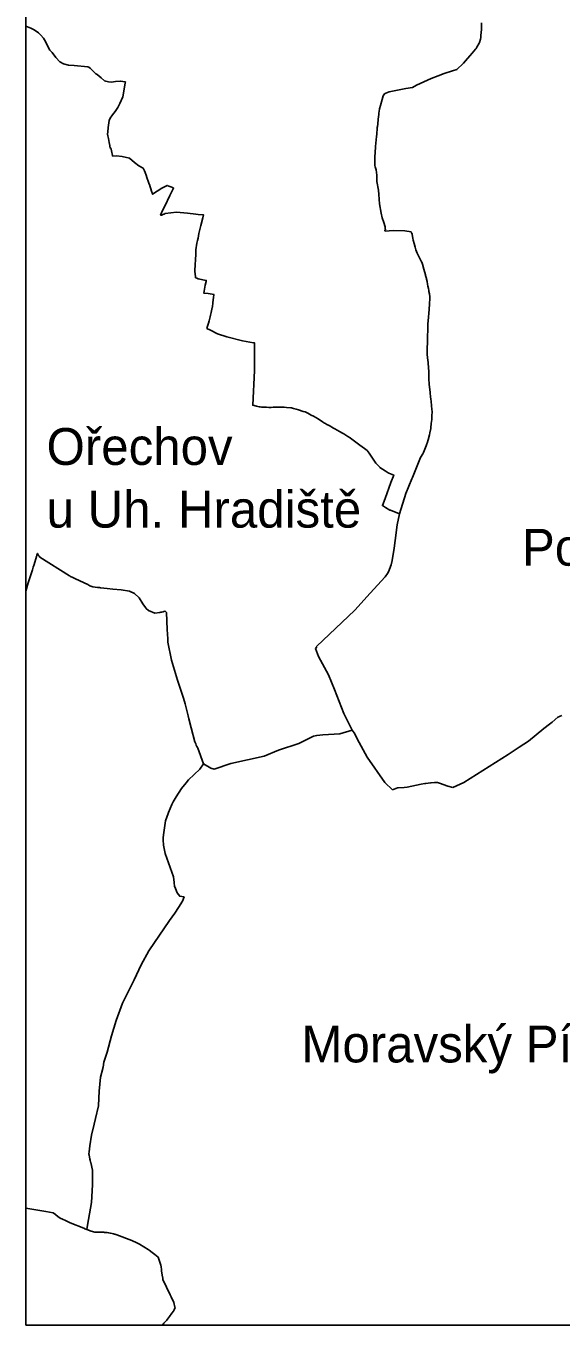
# Model space of a CAD drawing. Extents: x -552716 to -540720, y -1192685 to -1177912.
# Drawn here: x -549696 to -547709, y -1188366 to -1183546 of the extents above; entities that cross this region are included whole.
import ezdxf

# ---------------------------------------------------------------- set-up
doc = ezdxf.new("R2010")
doc.units = 0
doc.layers.add('Vrstva 1', color=7, linetype='Continuous')
doc.layers.add('Vrstva 60', color=7, linetype='Continuous')

msp = doc.modelspace()

# ---------------------------------------------------------------- linework, layer by layer
at = {"layer": 'Vrstva 1'}
for p, q in [((-548006.7, -1183581.2), (-548004.7, -1183558.7)), ((-548004.4, -1183547), (-548004.7, -1183533.8)), ((-548004.7, -1183558.7), (-548004.2, -1183553.8)), ((-548004.3, -1183552), (-548004.4, -1183547)), ((-548004.2, -1183553.8), (-548004.3, -1183552)), ((-548022.2, -1183624.6), (-548013.1, -1183609.1)), ((-548013.1, -1183609.1), (-548012.1, -1183607.4)), ((-548012.1, -1183607.4), (-548008.8, -1183594.9)), ((-548008.8, -1183594.9), (-548008.7, -1183594.2)), ((-548008.7, -1183594.2), (-548007.7, -1183588.1)), ((-548007.7, -1183588.1), (-548006.8, -1183582.7)), ((-548006.8, -1183582.7), (-548006.7, -1183581.2)), ((-548064, -1183675.4), (-548047.7, -1183656.8)), ((-548047.7, -1183656.8), (-548039.1, -1183646.4)), ((-548039.1, -1183646.4), (-548027, -1183631.6)), ((-548027, -1183631.6), (-548024.8, -1183628.9)), ((-548024.8, -1183628.9), (-548022.2, -1183624.6)), ((-548143.3, -1183722.5), (-548112.7, -1183712.6)), ((-548112.7, -1183712.6), (-548096.6, -1183707.4)), ((-548096.6, -1183707.4), (-548089.5, -1183700.7)), ((-548089.5, -1183700.7), (-548079.4, -1183691.2)), ((-548079.4, -1183691.2), (-548071.6, -1183684)), ((-548071.6, -1183684), (-548071.3, -1183683.6)), ((-548071.3, -1183683.6), (-548064, -1183675.4)), ((-548260.9, -1183773.8), (-548245.8, -1183765.2)), ((-548245.8, -1183765.2), (-548219, -1183753.4)), ((-548219, -1183753.4), (-548191.5, -1183741.2)), ((-548191.5, -1183741.2), (-548165.2, -1183730.9)), ((-548165.2, -1183730.9), (-548143.3, -1183722.5)), ((-548374, -1183818.8), (-548370.3, -1183805.3)), ((-548370.3, -1183805.3), (-548364.5, -1183797.2)), ((-548364.5, -1183797.2), (-548359.5, -1183795)), ((-548359.5, -1183795), (-548347.3, -1183789.6)), ((-548347.3, -1183789.6), (-548285.2, -1183778.3)), ((-548285.2, -1183778.3), (-548260.9, -1183773.8)), ((-548385.5, -1183868.9), (-548383.8, -1183854.5)), ((-548383.8, -1183854.5), (-548383.3, -1183852.7)), ((-548383.3, -1183852.7), (-548380.1, -1183840.7)), ((-548380.1, -1183840.7), (-548374, -1183818.8)), ((-548391.1, -1183918.4), (-548390.1, -1183909.8)), ((-548390.1, -1183909.8), (-548389.4, -1183904.1)), ((-548389.4, -1183904.1), (-548388.7, -1183897.4)), ((-548388.7, -1183897.4), (-548388, -1183891.4)), ((-548388, -1183891.4), (-548386.1, -1183874.7)), ((-548386.1, -1183874.7), (-548385.5, -1183868.9)), ((-548397.8, -1183993.5), (-548394.5, -1183955.3)), ((-548394.5, -1183955.3), (-548393.8, -1183947.2)), ((-548393.8, -1183947.2), (-548391.8, -1183924.9)), ((-548391.8, -1183924.9), (-548391.6, -1183923)), ((-548391.6, -1183923), (-548391.1, -1183918.4)), ((-548399.8, -1184016.1), (-548397.8, -1183993.5)), ((-548401, -1184061.4), (-548400.6, -1184046.8)), ((-548400.6, -1184046.8), (-548400.2, -1184030.6)), ((-548400.2, -1184030.6), (-548399.9, -1184016.3)), ((-548399.9, -1184016.3), (-548399.8, -1184016.1)), ((-548400.6, -1184062.9), (-548401, -1184061.4)), ((-548398.9, -1184068.6), (-548400.6, -1184062.9)), ((-548395.9, -1184079), (-548398.9, -1184068.6)), ((-548393.4, -1184099.7), (-548395.9, -1184079)), ((-548393.2, -1184123.4), (-548393.4, -1184099.7)), ((-548387.7, -1184155.4), (-548393.2, -1184123.4)), ((-548385.8, -1184171), (-548387.7, -1184155.4)), ((-548385.2, -1184188.9), (-548385.8, -1184171)), ((-548382.9, -1184206.2), (-548385.2, -1184188.9)), ((-548377.2, -1184240.8), (-548382.9, -1184206.2)), ((-548373.8, -1184257.4), (-548377.2, -1184240.8)), ((-548367.4, -1184274.9), (-548373.8, -1184257.4)), ((-548362, -1184291.2), (-548367.4, -1184274.9)), ((-548361.9, -1184294.6), (-548362, -1184291.2)), ((-548361.8, -1184297.2), (-548361.9, -1184294.6)), ((-548363.2, -1184302.9), (-548361.6, -1184302.8)), ((-548363.1, -1184304.2), (-548363.2, -1184302.9)), ((-548362.8, -1184307), (-548363.1, -1184304.2)), ((-548333.1, -1184304.8), (-548362.8, -1184307)), ((-548361.8, -1184298.9), (-548361.8, -1184297.2)), ((-548361.7, -1184300.9), (-548361.8, -1184298.9)), ((-548361.6, -1184301.8), (-548361.7, -1184300.9)), ((-548361.6, -1184302.8), (-548361.6, -1184301.8)), ((-548288.8, -1184306.2), (-548333.1, -1184304.8)), ((-548265.2, -1184310.1), (-548288.8, -1184306.2)), ((-548264.6, -1184314.4), (-548265.2, -1184310.1)), ((-548264.5, -1184314.7), (-548264.6, -1184314.4)), ((-548263, -1184314.7), (-548264.5, -1184314.7)), ((-548262.7, -1184318.2), (-548263, -1184314.7)), ((-548260.9, -1184327.4), (-548262.7, -1184318.2)), ((-548259.7, -1184333.5), (-548260.9, -1184327.4)), ((-548258.3, -1184340.5), (-548259.7, -1184333.5)), ((-548254.7, -1184353.3), (-548258.3, -1184340.5)), ((-548251, -1184366), (-548254.7, -1184353.3)), ((-548248.1, -1184376.4), (-548251, -1184366)), ((-548243.4, -1184388.5), (-548248.1, -1184376.4)), ((-548241.6, -1184393.3), (-548243.4, -1184388.5)), ((-548227.1, -1184421), (-548241.6, -1184393.3)), ((-548226.5, -1184422.1), (-548227.1, -1184421)), ((-548224.2, -1184429.8), (-548226.5, -1184422.1)), ((-548218.9, -1184447.9), (-548224.2, -1184429.8)), ((-548212.6, -1184469.4), (-548218.9, -1184447.9)), ((-548212.1, -1184471.5), (-548212.6, -1184469.4)), ((-548209.2, -1184483), (-548212.1, -1184471.5)), ((-548208.8, -1184484.7), (-548209.2, -1184483)), ((-548206.9, -1184494), (-548208.8, -1184484.7)), ((-548205, -1184503.2), (-548206.9, -1184494)), ((-548203.3, -1184511.3), (-548205, -1184503.2)), ((-548201.7, -1184519.5), (-548203.3, -1184511.3)), ((-548200.2, -1184527.7), (-548201.7, -1184519.5)), ((-548199.7, -1184530.7), (-548200.2, -1184527.7)), ((-548198.3, -1184540.2), (-548199.7, -1184530.7)), ((-548198.6, -1184591.1), (-548198.2, -1184582.5)), ((-548196.7, -1184550.6), (-548198.3, -1184540.2)), ((-548198.2, -1184582.5), (-548196.7, -1184550.6)), ((-548202.8, -1184639.3), (-548199.2, -1184598)), ((-548199.2, -1184598), (-548198.6, -1184591.1)), ((-548205.2, -1184701.7), (-548204.4, -1184669.7)), ((-548204.4, -1184669.7), (-548203.9, -1184653.7)), ((-548203.9, -1184650.9), (-548202.8, -1184639.3)), ((-548203.9, -1184653.7), (-548203.9, -1184650.9)), ((-548206.4, -1184745.6), (-548205.6, -1184716.2)), ((-548205.6, -1184716.2), (-548205.2, -1184701.7)), ((-548206.8, -1184762), (-548206.4, -1184745.6)), ((-548204.6, -1184778.7), (-548206.8, -1184762)), ((-548203.8, -1184785.1), (-548204.6, -1184778.7)), ((-548203, -1184796), (-548203.8, -1184785.1)), ((-548201.7, -1184813.7), (-548203, -1184796)), ((-548200.6, -1184828.4), (-548201.7, -1184813.7)), ((-548200.5, -1184830.3), (-548200.6, -1184828.4)), ((-548199.6, -1184857.9), (-548200.5, -1184830.3)), ((-548199, -1184872.6), (-548199.6, -1184857.9)), ((-548198.9, -1184875.3), (-548199, -1184872.6)), ((-548197.7, -1184886.6), (-548198.9, -1184875.3)), ((-548195.5, -1184905.2), (-548197.7, -1184886.6)), ((-548195.2, -1184908.1), (-548195.5, -1184905.2)), ((-548193.7, -1184920.7), (-548195.2, -1184908.1)), ((-548192.4, -1184932.4), (-548193.7, -1184920.7)), ((-548192, -1184936.7), (-548192.4, -1184932.4)), ((-548191.5, -1184941.7), (-548192, -1184936.7)), ((-548190.5, -1184951.3), (-548191.5, -1184941.7)), ((-548190, -1184956.1), (-548190.5, -1184951.3)), ((-548189.3, -1184966.2), (-548190, -1184956.1)), ((-548188.4, -1184979), (-548189.3, -1184966.2)), ((-548191.3, -1185022.6), (-548190.2, -1185012.7)), ((-548190.2, -1185012.7), (-548189.5, -1185007)), ((-548189.5, -1185007), (-548189.3, -1185001.8)), ((-548189.3, -1185001.8), (-548188.9, -1184991.1)), ((-548188.9, -1184991.1), (-548188.4, -1184979)), ((-548203.2, -1185081.1), (-548198.2, -1185062.8)), ((-548198.2, -1185062.8), (-548196.6, -1185055.1)), ((-548196.6, -1185055.1), (-548193.3, -1185039)), ((-548193.3, -1185039), (-548192.9, -1185036.1)), ((-548192.9, -1185036.1), (-548191.3, -1185022.6)), ((-548215, -1185115.8), (-548210.4, -1185103.9)), ((-548210.4, -1185103.9), (-548207.5, -1185096.4)), ((-548207.5, -1185096.4), (-548206.8, -1185094.1)), ((-548206.8, -1185094.1), (-548203.2, -1185081.1)), ((-548256.1, -1185209.4), (-548231.2, -1185147.6)), ((-548231.2, -1185147.6), (-548222, -1185134)), ((-548222, -1185134), (-548219.8, -1185128.2)), ((-548219.8, -1185128.2), (-548215, -1185115.8)), ((-548261.1, -1185221.7), (-548256.1, -1185209.4)), ((-548285, -1185280.5), (-548262.8, -1185225.8)), ((-548262.8, -1185225.8), (-548261.1, -1185221.7)), ((-548309, -1185355.8), (-548285, -1185280.5)), ((-548317.9, -1185397.5), (-548309, -1185355.8)), ((-548325.6, -1185454.8), (-548317.9, -1185397.5)), ((-548335.9, -1185528.9), (-548328.3, -1185483.6)), ((-548328.3, -1185483.6), (-548325.6, -1185454.8)), ((-548350.1, -1185570.8), (-548339.8, -1185544.8)), ((-548339.8, -1185544.8), (-548335.9, -1185528.9)), ((-548418.4, -1185650.6), (-548362.5, -1185589.4)), ((-548362.5, -1185589.4), (-548353.5, -1185578)), ((-548353.5, -1185578), (-548350.1, -1185570.8)), ((-548475, -1185713.1), (-548418.4, -1185650.6)), ((-548617.1, -1185848), (-548475, -1185713.1)), ((-548621.6, -1185855.7), (-548616.4, -1185850.1)), ((-548610.1, -1185885.7), (-548621.6, -1185855.7)), ((-548616.4, -1185850.1), (-548617.1, -1185848)), ((-548573.1, -1185953.8), (-548610.1, -1185885.7)), ((-548551, -1186008.4), (-548573.1, -1185953.8)), ((-548516.1, -1186097.6), (-548551, -1186008.4)), ((-548486.2, -1186156.6), (-548516.1, -1186097.6)), ((-547721.2, -1186110.7), (-547742.6, -1186128.8)), ((-547714.5, -1186108), (-547721.2, -1186110.7)), ((-547712.1, -1186107.1), (-547714.5, -1186108)), ((-547706.2, -1186104.7), (-547712.1, -1186107.1)), ((-548484.8, -1186159.4), (-548486.2, -1186156.6)), ((-548478, -1186168.9), (-548484.8, -1186159.4)), ((-548458.7, -1186204.9), (-548478, -1186168.9)), ((-547772.7, -1186153.1), (-547829.7, -1186199.2)), ((-547751.6, -1186136.1), (-547772.7, -1186153.1)), ((-547742.6, -1186128.8), (-547751.6, -1186136.1)), ((-548429.7, -1186259.2), (-548458.7, -1186204.9)), ((-547865.4, -1186221.9), (-547905.9, -1186248.9)), ((-547829.7, -1186199.2), (-547865.4, -1186221.9)), ((-548363.5, -1186352.8), (-548429.7, -1186259.2)), ((-547905.9, -1186248.9), (-548070.5, -1186352.8)), ((-548335.6, -1186380.3), (-548363.5, -1186352.8)), ((-548229, -1186359.6), (-548281.2, -1186370.3)), ((-548215.1, -1186357.4), (-548229, -1186359.6)), ((-548211.9, -1186356.8), (-548215.1, -1186357.4)), ((-548194.5, -1186354), (-548211.9, -1186356.8)), ((-548191.4, -1186353.9), (-548194.5, -1186354)), ((-548179.1, -1186353.5), (-548191.4, -1186353.9)), ((-548174.4, -1186353.3), (-548179.1, -1186353.5)), ((-548168.5, -1186353.1), (-548174.4, -1186353.3)), ((-548160.9, -1186355.8), (-548168.5, -1186353.1)), ((-548129.4, -1186367.3), (-548160.9, -1186355.8)), ((-548111.4, -1186372.1), (-548129.4, -1186367.3)), ((-548070.5, -1186352.8), (-548111.4, -1186372.1)), ((-548323, -1186375.8), (-548335.6, -1186380.3)), ((-548316.1, -1186373.3), (-548323, -1186375.8)), ((-548313.9, -1186372.5), (-548316.1, -1186373.3)), ((-548292.2, -1186371.1), (-548313.9, -1186372.5)), ((-548281.2, -1186370.3), (-548292.2, -1186371.1))]:
    msp.add_line(p, q, dxfattribs=at)
for points in [[(-549150.3, -1184145.8), (-549154.5, -1184143.8), (-549165.7, -1184139.6), (-549171.8, -1184137.4), (-549191.3, -1184147.2), (-549225.9, -1184170), (-549226.4, -1184168.6), (-549229.6, -1184158.8), (-549232.3, -1184150.6), (-549235.1, -1184142.2), (-549237.8, -1184133.7), (-549238.2, -1184132.5), (-549240.8, -1184125.3), (-549247, -1184107.9), (-549249.9, -1184099.7), (-549250.2, -1184099.1), (-549253.6, -1184089.1), (-549255.7, -1184083.2), (-549261.1, -1184072.9), (-549277.4, -1184064.2), (-549293.5, -1184051.9), (-549311.8, -1184036.1), (-549339.2, -1184030), (-549360.1, -1184028.1), (-549374.3, -1184028.7), (-549374.8, -1184026.8), (-549378.9, -1184008.9), (-549380.2, -1184003.3), (-549381.4, -1183998.2), (-549383.8, -1183998.1), (-549384.5, -1183993.2), (-549384.8, -1183989.8), (-549386.6, -1183977.8), (-549389.6, -1183963.7), (-549391.8, -1183953.1), (-549393.1, -1183947.6), (-549392.3, -1183939.1), (-549390.7, -1183922.9), (-549388.1, -1183904.9), (-549386.8, -1183896), (-549382.9, -1183888), (-549374.9, -1183875.3), (-549364.7, -1183863.2), (-549354.5, -1183848), (-549347.8, -1183833.7), (-549336.1, -1183808.3), (-549327.4, -1183758.3), (-549326.6, -1183753.5), (-549346.2, -1183750.2), (-549363.5, -1183752.3), (-549371, -1183753.1), (-549378.4, -1183754), (-549389.2, -1183753.3), (-549399.8, -1183750.8), (-549404.3, -1183748.8), (-549416.7, -1183737.7), (-549432.2, -1183726.3), (-549436.8, -1183722.9), (-549440.5, -1183719.5), (-549447.3, -1183712.2), (-549458, -1183702), (-549462, -1183698.2), (-549465.8, -1183697.8), (-549517.3, -1183692.5), (-549537.9, -1183690.9), (-549557, -1183685.9), (-549569.7, -1183678.4), (-549584.7, -1183662.8), (-549598.7, -1183644), (-549607.9, -1183635.3), (-549617.7, -1183616.7), (-549624.1, -1183603.6), (-549630.7, -1183591.5), (-549640.6, -1183580.4), (-549649.9, -1183571.6), (-549665.2, -1183559.4), (-549678.4, -1183553.7), (-549696, -1183546)], [(-548554.3, -1185037.9), (-548570.8, -1185028.5), (-548578.5, -1185024.2), (-548586.5, -1185019.6), (-548587.1, -1185019.3), (-548594.4, -1185014.7), (-548611.5, -1185003.9), (-548619.4, -1184998.9), (-548628.4, -1184994.2), (-548637.3, -1184989.5), (-548649.4, -1184983.1), (-548659.1, -1184978), (-548666.8, -1184975.8), (-548684.4, -1184970.7), (-548693.3, -1184968.2), (-548702.3, -1184965.6), (-548710.3, -1184963.3), (-548712.3, -1184962.7), (-548728.3, -1184961.3), (-548737.9, -1184960.4), (-548743, -1184960), (-548758.2, -1184960.2), (-548767.6, -1184960.3), (-548776.8, -1184960.4), (-548778.7, -1184960.4), (-548785.3, -1184961.7), (-548786, -1184961.9), (-548793.8, -1184961.4), (-548803.4, -1184960.8), (-548812.2, -1184960.3), (-548820.9, -1184959.8), (-548826.7, -1184959.4), (-548829.7, -1184958.7), (-548840.3, -1184956.4), (-548854.3, -1184953.2), (-548847.8, -1184824.4), (-548847.5, -1184818.4), (-548847.3, -1184722.1), (-548851.3, -1184721.4), (-548892, -1184714.2), (-548950.2, -1184699.3), (-548985.2, -1184687.8), (-549011.4, -1184675), (-549024, -1184668.9), (-549021.5, -1184659.3), (-549018.7, -1184648.8), (-549016.3, -1184639.4), (-549012.6, -1184625.6), (-549011, -1184619), (-549008.6, -1184608.8), (-549004.2, -1184590.8), (-549004, -1184589.5), (-549001.7, -1184571.8), (-548999.3, -1184553.7), (-548997.9, -1184543.3), (-548997.8, -1184542.3), (-549020.1, -1184538.4), (-549035.2, -1184537.3), (-549034.9, -1184529.3), (-549032, -1184515.5), (-549030.2, -1184507.1), (-549027.4, -1184494), (-549026.5, -1184489.8), (-549056.4, -1184483.9), (-549061, -1184482.1), (-549066.1, -1184480.1), (-549066.8, -1184476.2), (-549068.9, -1184455.5), (-549068.9, -1184452.2), (-549068.1, -1184433), (-549067.1, -1184411.6), (-549065.7, -1184394.9), (-549064.8, -1184376), (-549061.1, -1184351.6), (-549059.6, -1184341.3), (-549056.9, -1184333.6), (-549053.8, -1184315.7), (-549047.3, -1184286.6), (-549039.1, -1184258), (-549036.3, -1184247.1), (-549057.2, -1184244.7), (-549064.9, -1184243.8), (-549096.8, -1184240.1), (-549136.6, -1184236.5), (-549179, -1184242), (-549183, -1184243.7), (-549184.1, -1184244.2), (-549184.6, -1184244.4), (-549188.1, -1184245.9), (-549191.9, -1184247.7), (-549196.1, -1184247.6), (-549189.9, -1184232.4), (-549180.8, -1184214.2), (-549162.4, -1184174.7), (-549148, -1184147), (-549150.3, -1184145.8)], [(-548309, -1185355.8), (-548343, -1185343), (-548344.9, -1185341.9), (-548360.7, -1185332.6), (-548372.7, -1185325.5), (-548362, -1185299.4), (-548341.6, -1185240.1), (-548330.3, -1185212), (-548349.2, -1185204.6), (-548351.2, -1185203.8), (-548362.8, -1185196.2), (-548381.8, -1185183.6), (-548382.6, -1185182.9), (-548397.4, -1185167.9), (-548416.3, -1185138.2), (-548418.8, -1185134.3), (-548421.3, -1185131.3), (-548429.2, -1185121.6), (-548439.6, -1185113.8), (-548456.1, -1185101.4), (-548461.7, -1185097.3), (-548476.3, -1185086.3), (-548491.1, -1185075.2), (-548492.2, -1185074.5), (-548500.6, -1185069.4), (-548508.9, -1185064.3), (-548516.3, -1185059.8), (-548520.8, -1185057), (-548532.1, -1185050.6), (-548540.8, -1185045.6), (-548548.7, -1185041.1), (-548554.3, -1185037.9)], [(-549090.7, -1186117.3), (-549093.6, -1186105.7), (-549104.9, -1186061.5), (-549111.6, -1186040.4), (-549132.8, -1185973.5), (-549155.7, -1185898.6), (-549168.9, -1185832.1), (-549169.6, -1185819.5), (-549171.3, -1185785.6), (-549174.4, -1185721.9), (-549176.6, -1185719.8), (-549179.5, -1185717.1), (-549183.7, -1185718.8), (-549187.2, -1185720.2), (-549191.2, -1185720.8), (-549194.9, -1185721.3), (-549198.7, -1185721.8), (-549217, -1185724.2), (-549240.7, -1185714.9), (-549249.6, -1185707), (-549252.8, -1185704.3), (-549262.6, -1185689.8), (-549275.4, -1185667.9), (-549293.3, -1185651.6), (-549312.1, -1185643.4), (-549342, -1185638.4), (-549373.1, -1185635.2), (-549395.1, -1185632.9), (-549419.5, -1185630.4), (-549423.4, -1185630), (-549427.6, -1185629.5), (-549431, -1185629.2), (-549447.3, -1185627.5), (-549458.7, -1185622.7), (-549466.4, -1185618.8), (-549512.2, -1185596.8), (-549522.3, -1185591.9), (-549530.2, -1185588.1), (-549533.2, -1185586.6), (-549534.6, -1185585.9), (-549644.7, -1185516.8), (-549647.5, -1185513.2), (-549649.4, -1185510.6), (-549653.7, -1185502.8), (-549655.5, -1185509), (-549657.1, -1185514.3), (-549666, -1185544.5), (-549668.8, -1185554.1), (-549671.9, -1185563.5), (-549674.7, -1185571.7), (-549688.1, -1185611.6), (-549696, -1185643.5)], [(-549037.3, -1186284.1), (-549058.4, -1186225.9), (-549059.7, -1186223), (-549061.4, -1186219.1), (-549063.6, -1186214.3), (-549065.4, -1186210), (-549068.6, -1186202.8), (-549082.4, -1186149.7), (-549090.7, -1186117.3)], [(-549459, -1187701.4), (-549453.1, -1187661.8), (-549443.4, -1187620.4), (-549438.2, -1187600.1), (-549426.3, -1187552.7), (-549426.3, -1187552.1), (-549424.3, -1187498.5), (-549419.1, -1187447), (-549411.2, -1187413.9), (-549410.7, -1187412), (-549410, -1187408.9), (-549407.3, -1187390.6), (-549394.4, -1187354), (-549378.6, -1187293.5), (-549360.6, -1187236.1), (-549337.2, -1187171.9), (-549293.9, -1187084.8), (-549268.8, -1187029.2), (-549239.6, -1186977.6), (-549162.8, -1186865.8), (-549143.4, -1186837.8), (-549129.1, -1186816.9), (-549114.5, -1186793.4), (-549111.8, -1186787), (-549108.8, -1186777.5), (-549117.1, -1186776.4), (-549124.2, -1186775.4), (-549125.1, -1186775.3), (-549134.1, -1186762.2), (-549140.7, -1186746.1), (-549144, -1186738.1), (-549145.6, -1186725.1), (-549145.6, -1186724.7), (-549145.7, -1186724.1), (-549148.2, -1186702.9), (-549179.6, -1186616.9), (-549185.4, -1186585.4), (-549186.3, -1186566.3), (-549186.7, -1186557.7), (-549184.2, -1186538.8), (-549178.5, -1186495.7), (-549168.5, -1186467.7), (-549167.1, -1186463.9), (-549154.3, -1186435.3), (-549149.3, -1186424.3), (-549138, -1186406.1), (-549118.8, -1186375.4), (-549101.8, -1186354), (-549093, -1186342.7), (-549050.1, -1186303.3), (-549037.3, -1186284.1), (-549009.9, -1186300.3), (-548997.2, -1186304.1), (-548935.2, -1186282.3), (-548811.8, -1186255.1), (-548758.3, -1186232.7), (-548683.1, -1186208.7), (-548628, -1186181.3), (-548616.1, -1186178.2), (-548594.2, -1186176), (-548531.2, -1186172.2), (-548484.8, -1186159.4)], [(-549101.8, -1186354), (-549118.8, -1186375.4), (-549138, -1186406.1), (-549149.3, -1186424.3), (-549154.3, -1186435.3), (-549167.1, -1186463.9), (-549168.5, -1186467.7), (-549178.5, -1186495.7), (-549184.2, -1186538.8), (-549186.7, -1186557.7), (-549186.3, -1186566.3), (-549185.4, -1186585.4), (-549179.6, -1186616.9), (-549148.2, -1186702.9), (-549145.7, -1186724.1), (-549145.6, -1186724.7), (-549145.6, -1186725.1), (-549144, -1186738.1), (-549140.7, -1186746.1), (-549134.1, -1186762.2), (-549125.1, -1186775.3), (-549124.2, -1186775.4), (-549117.1, -1186776.4), (-549108.8, -1186777.5), (-549111.8, -1186787), (-549114.5, -1186793.4), (-549129.1, -1186816.9), (-549143.4, -1186837.8), (-549162.8, -1186865.8), (-549239.6, -1186977.6), (-549268.8, -1187029.2), (-549293.9, -1187084.8), (-549337.2, -1187171.9), (-549360.6, -1187236.1), (-549378.6, -1187293.5), (-549394.4, -1187354), (-549407.3, -1187390.6), (-549410, -1187408.9), (-549410.7, -1187412), (-549411.2, -1187413.9), (-549419.1, -1187447), (-549424.3, -1187498.5), (-549426.3, -1187552.1), (-549426.3, -1187552.7), (-549438.2, -1187600.1), (-549443.4, -1187620.4), (-549453.1, -1187661.8), (-549459, -1187701.4), (-549460.2, -1187712), (-549461.6, -1187723.5), (-549462.5, -1187731.2), (-549462.4, -1187731.8), (-549461.7, -1187735.2), (-549461.5, -1187735.9), (-549460.1, -1187742.4), (-549459.8, -1187743.6), (-549458.5, -1187749.8), (-549458.4, -1187750.4), (-549457.3, -1187755.2), (-549455.9, -1187761.8), (-549455.6, -1187763.3), (-549449.6, -1187791.3), (-549448.5, -1187846), (-549452.2, -1187912.1), (-549467.3, -1187995.9), (-549467.3, -1187996.2), (-549470.2, -1188012.2), (-549473.9, -1188010.7), (-549477.7, -1188009.1), (-549479.2, -1188008.5), (-549481.7, -1188007.5), (-549531.9, -1187986.8), (-549549.6, -1187978.5), (-549560.2, -1187973.6), (-549568.9, -1187969.6), (-549570.8, -1187968.8), (-549576.2, -1187964.5), (-549586.8, -1187956.2), (-549595, -1187949.7), (-549622, -1187945.4), (-549696, -1187932.9)], [(-549189.6, -1188366.4), (-549183.7, -1188359.7), (-549177.2, -1188352.3), (-549173.3, -1188347.9), (-549171.1, -1188345.1), (-549163, -1188334.5), (-549154.2, -1188323), (-549148.1, -1188315), (-549146.2, -1188310.3), (-549142.6, -1188301.2), (-549143.1, -1188299.7), (-549147.6, -1188283.4), (-549157.5, -1188261.9), (-549161, -1188254.4), (-549187.3, -1188197.4), (-549188.3, -1188192.3), (-549190.6, -1188181.5), (-549192.6, -1188165.2), (-549193.1, -1188160.8), (-549194.5, -1188150.2), (-549195.2, -1188144), (-549199.9, -1188129.6), (-549200.1, -1188129.2), (-549204.8, -1188114.8), (-549217.6, -1188105), (-549217.7, -1188104.9), (-549228, -1188097), (-549239, -1188088.5), (-549242.2, -1188086.4), (-549274, -1188066), (-549284.5, -1188061.1), (-549302.7, -1188052.7), (-549358.1, -1188031.9), (-549366.2, -1188028.9), (-549366.9, -1188028.7), (-549371.6, -1188027.8), (-549375.5, -1188027), (-549382.3, -1188025.6), (-549382.4, -1188025.6), (-549388.2, -1188024.4), (-549389.6, -1188024.1), (-549394.2, -1188023.2), (-549396.3, -1188022.7), (-549398.1, -1188022.7), (-549399.7, -1188022.6), (-549400.1, -1188022.6), (-549403.9, -1188022.5), (-549407, -1188022.4), (-549408.1, -1188022.3), (-549413.2, -1188022.2), (-549413.9, -1188022.2), (-549416.5, -1188022.1), (-549417.1, -1188022), (-549417.3, -1188022), (-549421.3, -1188021.9), (-549422.5, -1188021.9), (-549440.6, -1188021.2), (-549454.4, -1188018.7), (-549470.2, -1188012.2)]]:
    msp.add_lwpolyline(points, dxfattribs=at)
at = {"layer": 'Vrstva 60'}
msp.add_lwpolyline([(-543896.1, -1181161.6), (-549696, -1181161.6), (-549696, -1188366.4), (-543896.1, -1188366.4)], close=True, dxfattribs=at)

# ---------------------------------------------------------------- texts
at = {"layer": 'Vrstva 1'}
for s, height, p in [('Ořechov', 136.69, (-549619.5, -1185174.5)), ('u Uh. Hradiště', 136.688, (-549619.5, -1185407.3)), ('Polešovice', 136.69, (-547854.4, -1185548.5)), ('Moravský Písek', 136.688, (-548673.3, -1187391.9))]:
    msp.add_text(s, height=height, dxfattribs=at).set_placement(p)

doc.saveas('drawing.dxf')
